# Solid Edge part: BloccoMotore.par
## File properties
Author: Administrator
Template: Normal.par
Last saved by: Luca
Revision: 13
Application: Solid Edge
Precisione: 0.99
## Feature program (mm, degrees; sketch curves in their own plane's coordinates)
sketch for "unnamed Protrusion 1" plane through (0, 0, 0) normal (0, 0, 1) x-axis (1, 0, 0)
  line (-60, -60) -> (60, -60)
  line (60, -60) -> (60, 60)
  line (60, 60) -> (-60, 60)
  line (-60, 60) -> (-60, -60)
  dimension (linear) = 60
  dimension (linear) = 60
extrude "unnamed Protrusion 1" add finite 250 along -normal
sketch for "ExtrudedCutout_2" plane through (0, 0, 0) normal (0, -1, 0) x-axis (1, 0, 0)
  line (-55, -190) -> (-55, -130)
  line (-55, -130) -> (55, -130)
  line (55, -190) -> (55, -130)
  arc centre (0, -190) radius 55 from (55, -190) to (-55, -190) cw
extrude "ExtrudedCutout_2" cut finite 17 along -normal
sketch for "ExtrudedProtrusion_3" plane through (0, 17, -137.5) normal (0, -1, 0) x-axis (1, 0, 0)
extrude "ExtrudedProtrusion_3" add finite 1 along +normal
sketch for "ExtrudedCutout_11" plane through (0, 16, -137.5) normal (0, -1, 0) x-axis (1, 0, 0)
  circle centre (0, -52.5) radius 25
extrude "ExtrudedCutout_11" cut finite 12 along -normal
sketch for "ExtrudedCutout_4" plane through (0, 60, -100) normal (0, 1, 0) x-axis (1, 0, 0)
  line (-55, 55) -> (55, 55)
  line (55, 55) -> (55, 145)
  line (55, 145) -> (-55, 145)
  line (-55, 145) -> (-55, 55)
extrude "ExtrudedCutout_4" cut finite 33 along -normal
fillet "Rotondo_1" radius 20
fillet "Rotondo_3" radius 12
fillet "Rotondo_4" radius 1
fillet "Rotondo_5" radius 1
mirror "unnamed Mirror 1" of "ExtrudedCutout_2", "ExtrudedProtrusion_3", "ExtrudedCutout_11", "ExtrudedCutout_4", "Rotondo_4", "Rotondo_5", "Rotondo_1", "Rotondo_3" about plane through (0, 0, 0) normal (0, -1, 0)
extrude "unnamed Cutout 1" cut finite 17
extrude "unnamed Protrusion 2" add finite 1
extrude "unnamed Cutout 2" cut finite 12
extrude "unnamed Cutout 3" cut finite 33
fillet "unnamed Round 1"
fillet "unnamed Round 2"
fillet "unnamed Round 3"
fillet "unnamed Round 4"
fillet "Rotondo_25" radius 25
sketch for "ExtrudedCutout_8" plane through (0, 0, 0) normal (0, 0, 1) x-axis (0, 1, 0)
  circle centre (0, 0) radius 48.2
extrude "ExtrudedCutout_8" cut finite 145 along -normal
fillet "Rotondo_26" radius 5
fillet "Rotondo_28" radius 12
fillet "Rotondo_29" radius 8
sketch for "ExtrudedCutout_30" plane through (0, 0, 0) normal (0, -1, 0) x-axis (1, 0, 0)
  arc centre (0, -190) radius 60 from (60, -190) to (-60, -190) cw
  line (-60, -190) -> (-83.2314, -190)
  line (-83.2314, -190) -> (-83.2314, -275.2301)
  line (-83.2314, -275.2301) -> (94.4319, -275.2301)
  line (94.4319, -275.2301) -> (94.4319, -190)
  line (94.4319, -190) -> (60, -190)
extrude "ExtrudedCutout_30" cut finite 40 symmetric
fillet "Rotondo_32" radius 5
sketch for "ExtrudedCutout_31" #1 plane through (0, 0, 0) normal (0, 0, 1) x-axis (-1, 0, 0)
  line (-60, 60) -> (-60, 41)
  line (-60, 41) -> (-46, 41)
  line (-46, 41) -> (-46, 60)
  line (-46, 60) -> (-60, 60)
sketch for "ExtrudedCutout_31" #2 plane through (0, 0, 0) normal (0, 0, 1) x-axis (-1, 0, 0)
  arc centre (0, 0) radius 52 from (0, 52) to (-28.3636, 43.5833) ccw
  arc centre (-30, 46.0977) radius 3 from (-32.2981, 44.1694) to (-28.3636, 43.5833) ccw
  line (-32.2981, 44.1694) -> (-33.2981, 45.3611)
  arc centre (-31, 47.2895) radius 3 from (-33.2981, 45.3611) to (-34, 47.2895) cw
  line (-34, 60) -> (-34, 47.2895)
  line (0, 60) -> (-34, 60)
  line (0, 52) -> (0, 60)
sketch for "ExtrudedCutout_31" #3 plane through (0, 0, 0) normal (0, 0, 1) x-axis (-1, 0, 0)
  line (-48.3037, -39) -> (-53, -39)
  arc centre (-53, -34) radius 5 from (-58, -34) to (-53, -39) ccw
  line (-58, -34) -> (-58, -6)
  arc centre (-56, -6) radius 2 from (-58, -6) to (-56, -4) cw
  line (-54.1687, -4) -> (-56, -4)
  arc centre (-54.1687, -6) radius 2 from (-54.1687, -4) to (-52.1809, -5.7798) cw
  arc centre (0, 0) radius 52.5 from (-52.1809, -5.7798) to (-43.3495, -29.6154) ccw
  arc centre (-48.3037, -33) radius 6 from (-43.3495, -29.6154) to (-48.3037, -39) cw
sketch for "ExtrudedCutout_31" #4 plane through (0, 0, 0) normal (0, 0, 1) x-axis (-1, 0, 0)
  line (-60, -60) -> (-60, -41)
  line (-60, -41) -> (-46, -41)
  line (-46, -41) -> (-46, -60)
  line (-46, -60) -> (-60, -60)
sketch for "ExtrudedCutout_31" #5 plane through (0, 0, 0) normal (0, 0, 1) x-axis (-1, 0, 0)
  arc centre (0, 0) radius 52 from (0, -52) to (-28.3636, -43.5833) cw
  arc centre (-30, -46.0977) radius 3 from (-32.2981, -44.1694) to (-28.3636, -43.5833) cw
  line (-32.2981, -44.1694) -> (-33.2981, -45.3611)
  arc centre (-31, -47.2895) radius 3 from (-33.2981, -45.3611) to (-34, -47.2895) ccw
  line (-34, -60) -> (-34, -47.2895)
  line (0, -60) -> (-34, -60)
  line (0, -52) -> (0, -60)
sketch for "ExtrudedCutout_31" #6 plane through (0, 0, 0) normal (0, 0, 1) x-axis (-1, 0, 0)
  line (48.3037, -39) -> (53, -39)
  arc centre (53, -34) radius 5 from (58, -34) to (53, -39) cw
  line (58, -34) -> (58, -6)
  arc centre (56, -6) radius 2 from (58, -6) to (56, -4) ccw
  line (54.1687, -4) -> (56, -4)
  arc centre (54.1687, -6) radius 2 from (54.1687, -4) to (52.1809, -5.7798) ccw
  arc centre (0, 0) radius 52.5 from (52.1809, -5.7798) to (43.3495, -29.6154) cw
  arc centre (48.3037, -33) radius 6 from (43.3495, -29.6154) to (48.3037, -39) ccw
sketch for "ExtrudedCutout_31" #7 plane through (0, 0, 0) normal (0, 0, 1) x-axis (-1, 0, 0)
  line (60, -60) -> (60, -41)
  line (60, -41) -> (46, -41)
  line (46, -41) -> (46, -60)
  line (46, -60) -> (60, -60)
sketch for "ExtrudedCutout_31" #8 plane through (0, 0, 0) normal (0, 0, 1) x-axis (-1, 0, 0)
  arc centre (0, 0) radius 52 from (0, -52) to (28.3636, -43.5833) ccw
  arc centre (30, -46.0977) radius 3 from (32.2981, -44.1694) to (28.3636, -43.5833) ccw
  line (32.2981, -44.1694) -> (33.2981, -45.3611)
  arc centre (31, -47.2895) radius 3 from (33.2981, -45.3611) to (34, -47.2895) cw
  line (34, -60) -> (34, -47.2895)
  line (0, -60) -> (34, -60)
  line (0, -52) -> (0, -60)
sketch for "ExtrudedCutout_31" #9 plane through (0, 0, 0) normal (0, 0, 1) x-axis (-1, 0, 0)
  line (48.3037, 39) -> (53, 39)
  arc centre (53, 34) radius 5 from (58, 34) to (53, 39) ccw
  line (58, 34) -> (58, 6)
  arc centre (56, 6) radius 2 from (58, 6) to (56, 4) cw
  line (54.1687, 4) -> (56, 4)
  arc centre (54.1687, 6) radius 2 from (54.1687, 4) to (52.1809, 5.7798) cw
  arc centre (0, 0) radius 52.5 from (52.1809, 5.7798) to (43.3495, 29.6154) ccw
  arc centre (48.3037, 33) radius 6 from (43.3495, 29.6154) to (48.3037, 39) cw
sketch for "ExtrudedCutout_31" #10 plane through (0, 0, 0) normal (0, 0, 1) x-axis (-1, 0, 0)
  line (60, 60) -> (60, 41)
  line (60, 41) -> (46, 41)
  line (46, 41) -> (46, 60)
  line (46, 60) -> (60, 60)
sketch for "ExtrudedCutout_31" #11 plane through (0, 0, 0) normal (0, 0, 1) x-axis (-1, 0, 0)
  arc centre (0, 0) radius 52 from (0, 52) to (28.3636, 43.5833) cw
  arc centre (30, 46.0977) radius 3 from (32.2981, 44.1694) to (28.3636, 43.5833) cw
  line (32.2981, 44.1694) -> (33.2981, 45.3611)
  arc centre (31, 47.2895) radius 3 from (33.2981, 45.3611) to (34, 47.2895) ccw
  line (34, 60) -> (34, 47.2895)
  line (0, 60) -> (34, 60)
  line (0, 52) -> (0, 60)
sketch for "ExtrudedCutout_31" #12 plane through (0, 0, 0) normal (0, 0, 1) x-axis (-1, 0, 0)
  line (-48.3037, 39) -> (-53, 39)
  arc centre (-53, 34) radius 5 from (-58, 34) to (-53, 39) cw
  line (-58, 34) -> (-58, 6)
  arc centre (-56, 6) radius 2 from (-58, 6) to (-56, 4) ccw
  line (-54.1687, 4) -> (-56, 4)
  arc centre (-54.1687, 6) radius 2 from (-54.1687, 4) to (-52.1809, 5.7798) ccw
  arc centre (0, 0) radius 52.5 from (-52.1809, 5.7798) to (-43.3495, 29.6154) cw
  arc centre (-48.3037, 33) radius 6 from (-43.3495, 29.6154) to (-48.3037, 39) ccw
  dimension (linear) = 30
extrude "ExtrudedCutout_31" cut finite 120 along -normal
sketch for "unnamed Cutout 4" #1 plane through (0, 0, 0) normal (0, 0, 1) x-axis (0, 1, 0)
  line (52, 65.9599) -> (52, -64.5155)
  line (74.5058, -64.5155) -> (52, -64.5155)
  line (76.9131, 65.9599) -> (74.5058, -64.5155)
  line (52, 65.9599) -> (76.9131, 65.9599)
sketch for "unnamed Cutout 4" #2 plane through (0, 0, 0) normal (0, 0, 1) x-axis (0, 1, 0)
  line (-52, 71.9781) -> (-52, -70.0523)
  line (-74.9872, -70.0523) -> (-52, -70.0523)
  line (-74.9872, 71.9781) -> (-74.9872, -70.0523)
  line (-52, 71.9781) -> (-74.9872, 71.9781)
extrude "unnamed Cutout 4" cut through along -normal
sketch for "unnamed Cutout 5" #1 plane through (0, 0, 0) normal (0, 0, 1) x-axis (0, 1, 0)
  circle centre (-43, 40) radius 5
sketch for "unnamed Cutout 5" #2 plane through (0, 0, 0) normal (0, 0, 1) x-axis (0, 1, 0)
  circle centre (43, 40) radius 5
sketch for "unnamed Cutout 5" #3 plane through (0, 0, 0) normal (0, 0, 1) x-axis (0, 1, 0)
  circle centre (43, -40) radius 5
sketch for "unnamed Cutout 5" #4 plane through (0, 0, 0) normal (0, 0, 1) x-axis (0, 1, 0)
  circle centre (-43, -40) radius 5
extrude "unnamed Cutout 5" cut through along -normal
fillet "Rotondo_35" radius 8
fillet "Rotondo_37" radius 7
fillet "Rotondo_38" radius 6
sketch for "unnamed Cutout 6" plane through (0, 0, 0) normal (0, -1, 0) x-axis (1, 0, 0)
extrude "unnamed Cutout 6" cut through along +normal
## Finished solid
Body 1: solid body, 127 faces, 315 edges, 190 vertices.
  Faces by surface: cylinder 53, plane 36, blend 19, torus 13, spline 6
  Edges by curve: line 133, circle 121, intersection 39, curve on surface 12, spline 6, ellipse 4
Bounding box of the edges (mm; curved faces can reach further): 120.000 x 52.000 x 250.516, from (-60, 0, -250.5163) to (60, 52, 0).
Cylindrical faces by radius (mm): R1 x2, R2 x4, R3 x4, R5 x12, R6 x4, R7 x2, R8 x5, R12 x5, R20 x6, R25 x3, R48.2 x1, R52 x1, R52.5 x2, R55 x1, R60 x1
Toroidal faces (ring radius, tube radius in mm): R2 r6 x2, R8 r12 x4, R20 r5 x2, R31 r1 x1, R36.2 r12 x1, R54 r1 x1, R65 r5 x2
Planar faces by outward normal: +x 6, +y 6, +z 7, -x 6, -y 7, -z 2, oblique 2
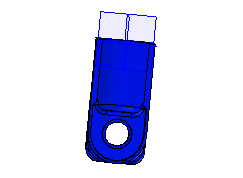
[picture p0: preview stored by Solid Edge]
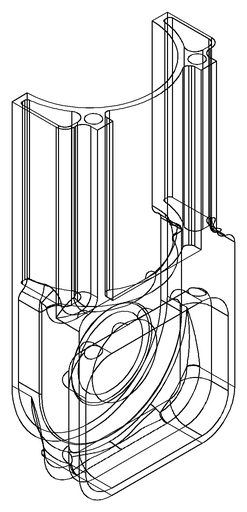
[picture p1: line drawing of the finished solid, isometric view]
